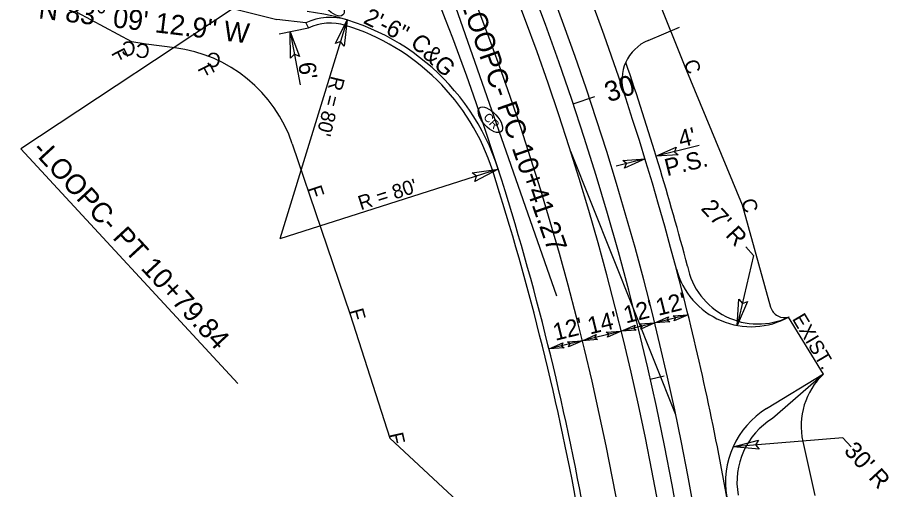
# Model space of a CAD drawing. Extents: x 1702862 to 1704514, y 793768 to 796215.
# Drawn here: x 1703743.4 to 1704047.6, y 794306.9 to 794472 of the extents above; entities that cross this region are included whole.
import ezdxf

# ---------------------------------------------------------------- set-up
doc = ezdxf.new("R2010")
doc.units = 0
for name, color, linetype in [('Prop Conc 2ft 6in Curb and Gutter', 7, 'Continuous'), ('Prop Dimension', 7, 'Continuous'), ('Prop Dimension Text', 7, 'Continuous'), ('Prop DSN Text', 7, 'Continuous'), ('Prop EOT', 7, 'Continuous'), ('Prop Horizontal Alignment', 7, 'Continuous'), ('Prop Horizontal Alignment Curve and Spiral Data', 7, 'Continuous'), ('Prop Horizontal Alignment Direction Label', 7, 'Continuous'), ('Prop Horizontal Alignment Station Label', 7, 'Continuous'), ('Prop Horizontal Alignment Tick Label', 7, 'Continuous'), ('Prop Horizontal Alignment Tick Large', 7, 'Continuous'), ('Prop Horizontal Alignment Tick Small', 7, 'Continuous'), ('Prop Lane Lines', 7, 'Continuous'), ('Prop Paved Shoulder', 7, 'Continuous'), ('Prop SS Cut Line', 7, 'Continuous'), ('Prop SS Fill Line', 7, 'Continuous'), ('Prop SS Misc', 7, 'Continuous'), ('Prop SS Transition Line', 7, 'Continuous'), ('Prop Terminator CELL', 7, 'Continuous'), ('Prop WCR CELL', 7, 'Continuous')]:
    doc.layers.add(name, color=color, linetype=linetype)

msp = doc.modelspace()

# ---------------------------------------------------------------- linework, layer by layer
at = {"layer": 'Prop Conc 2ft 6in Curb and Gutter'}
for centre, radius, start, end in [((1703852.67, 794451.95), 18, 72.9584, 115.227), ((1703835.09, 794394.58), 78, 17.697, 72.9584), ((1702989.11, 794124.65), 966, 10.14602, 17.69698)]:
    msp.add_arc(centre, radius, start, end, dxfattribs=at)
at = {"layer": 'Prop Dimension'}
for p, q in [((1703858.53, 794471.07), (1703835.09, 794394.58)), ((1703845, 794468.23), (1703834.87, 794466.1)), ((1703838.68, 794466.9), (1703842.13, 794448.38)), ((1703981.48, 794427.14), (1703966.46, 794423.44)), ((1703962.57, 794422.48), (1703952.5, 794420)), ((1703911.3, 794418.9), (1703835.09, 794394.58)), ((1703977.58, 794368.05), (1703960.1, 794363.75)), ((1703960.1, 794363.75), (1703929.03, 794356.1))]:
    msp.add_line(p, q, dxfattribs=at)
for points in [[(1703997.7, 794391.74), (1704000.49, 794388.71), (1703994.76, 794364.3)], [(1704034.48, 794321.92), (1704031.62, 794325.02), (1703993.3, 794321.91)]]:
    msp.add_lwpolyline(points, dxfattribs=at)
at = {"layer": 'Prop EOT'}
for p, q in [((1703844.15, 794470.04), (1703845, 794468.23)), ((1703963.67, 794463.92), (1703974.65, 794468.55)), ((1704024.85, 794347.32), (1704012.71, 794367.19)), ((1704024.85, 794347.32), (1704005.02, 794335.21))]:
    msp.add_line(p, q, dxfattribs=at)
for centre, radius, start, end in [((1702989.11, 794124.65), 1018, 14.75888, 42.70907), ((1703835.09, 794394.58), 80, 17.697, 83.1536), ((1703852.67, 794451.95), 20, 72.9584, 115.227), ((1703969.5, 794450.1), 15, 112.8746, 198.3644), ((1702989.11, 794124.65), 968, 10.14602, 17.69698), ((1703999.63, 794390.86), 27, 194.7589, 299.2661), ((1704020.66, 794309.61), 30, 121.4124, 190.1653)]:
    msp.add_arc(centre, radius, start, end, dxfattribs=at)
at = {"layer": 'Prop Horizontal Alignment'}
msp.add_arc((1702989.11, 794124.65), 1000, 351.25916, 42.70907, dxfattribs=at)
at = {"layer": 'Prop Horizontal Alignment Curve and Spiral Data'}
msp.add_line((1703744.62, 794426.04), (1703820.33, 794344.01), dxfattribs=at)
at = {"layer": 'Prop Horizontal Alignment Station Label'}
msp.add_line((1703836.77, 794487.04), (1703744.62, 794426.04), dxfattribs=at)
msp.add_lwpolyline([(1703895.55, 794478.02), (1703931.64, 794374.68)], dxfattribs=at)
at = {"layer": 'Prop Horizontal Alignment Tick Large'}
msp.add_line((1703937.48, 794441.8), (1703945.07, 794444.34), dxfattribs=at)
at = {"layer": 'Prop Horizontal Alignment Tick Small'}
msp.add_line((1703964.41, 794345.53), (1703969.29, 794346.64), dxfattribs=at)
at = {"layer": 'Prop Lane Lines'}
msp.add_line((1703973.28, 794333.07), (1703936.62, 794425.07), dxfattribs=at)
for radius, start, end in [(1006, 0.00687, 42.70907), (994, 359.40932, 42.70907), (980, 359.40932, 42.70907), (968, 17.6382, 31.00789), (1018, 10.1653, 14.75888)]:
    msp.add_arc((1702989.11, 794124.65), radius, start, end, dxfattribs=at)
at = {"layer": 'Prop Paved Shoulder'}
for p, q in [((1703803.86, 794478.91), (1703834.03, 794471.26)), ((1703844.15, 794470.04), (1703834.03, 794471.26)), ((1704024.85, 794347.32), (1704007.11, 794331.8))]:
    msp.add_line(p, q, dxfattribs=at)
for centre, radius, start, end in [((1702989.11, 794124.65), 1022, 14.75888, 18.93305), ((1704001.96, 794389.87), 25.05, 191.2148, 295.722), ((1704020.66, 794309.61), 26, 121.4124, 190.1653)]:
    msp.add_arc(centre, radius, start, end, dxfattribs=at)
at = {"layer": 'Prop SS Cut Line'}
for p, q in [((1703788.36, 794462.65), (1703783.41, 794463.43)), ((1703976.48, 794454.84), (1703996.51, 794406.41)), ((1703996.51, 794406.41), (1704006.42, 794370.71)), ((1704017.63, 794323.78), (1704021.82, 794304.82))]:
    msp.add_line(p, q, dxfattribs=at)
for centre, radius, start, end in [((1704011.24, 794372.05), 5, 195.5278, 288.5337), ((1704042.04, 794329.17), 25, 133.4523, 192.4595)]:
    msp.add_arc(centre, radius, start, end, dxfattribs=at)
at = {"layer": 'Prop SS Fill Line'}
for p, q in [((1703788.36, 794462.65), (1703783.41, 794463.43)), ((1703839.4, 794427.8), (1703859.6, 794368.12)), ((1703859.6, 794368.12), (1703873.4, 794324.92)), ((1703873.4, 794324.92), (1703911.44, 794289.63))]:
    msp.add_line(p, q, dxfattribs=at)
msp.add_arc((1703792.04, 794411.78), 50, 18.6944, 82.73, dxfattribs=at)
at = {"layer": 'Prop SS Transition Line'}
for p, q in [((1703957.17, 794503.16), (1703976.48, 794454.84)), ((1703783.41, 794463.43), (1703764.24, 794473.69)), ((1703798.37, 794461.37), (1703788.36, 794462.65))]:
    msp.add_line(p, q, dxfattribs=at)
at = {"layer": 'Prop Terminator CELL'}
for points in [[(1703854.47, 794462.89), (1703858.53, 794471.07), (1703857.47, 794461.94), (1703856.27, 794463.5)], [(1703838.81, 794457.77), (1703838.68, 794466.9), (1703841.91, 794458.3), (1703840.13, 794459.14)], [(1703974.08, 794423.96), (1703966.34, 794423.41), (1703973.48, 794426.57), (1703972.86, 794425.01)], [(1703954.82, 794421.93), (1703962.57, 794422.48), (1703955.42, 794419.32), (1703956.05, 794420.87)], [(1703902.25, 794417.67), (1703911.3, 794418.9), (1703903.16, 794414.65), (1703903.77, 794416.52)], [(1703998.33, 794372.71), (1703994.76, 794364.3), (1703995.27, 794373.48), (1703996.57, 794372)], [(1703971.17, 794365.56), (1703965.93, 794365.18), (1703970.76, 794367.32), (1703970.34, 794366.27)], [(1703972.34, 794367.68), (1703977.58, 794368.05), (1703972.75, 794365.92), (1703973.17, 794366.97)], [(1703959.52, 794362.69), (1703954.28, 794362.32), (1703959.11, 794364.45), (1703958.69, 794363.4)], [(1703960.69, 794364.81), (1703965.93, 794365.18), (1703961.1, 794363.05), (1703961.52, 794364.1)], [(1703945.92, 794359.34), (1703940.68, 794358.97), (1703945.52, 794361.11), (1703945.09, 794360.05)], [(1703949.04, 794361.94), (1703954.28, 794362.32), (1703949.44, 794360.18), (1703949.87, 794361.23)], [(1703934.27, 794356.47), (1703929.03, 794356.1), (1703933.86, 794358.24), (1703933.44, 794357.18)], [(1703935.45, 794358.6), (1703940.68, 794358.97), (1703935.85, 794356.83), (1703936.27, 794357.88)], [(1704002.39, 794321.09), (1703993.3, 794321.91), (1704002.19, 794324.24), (1704001.17, 794322.55)]]:
    msp.add_lwpolyline(points, close=True, dxfattribs=at)
at = {"layer": 'Prop WCR CELL'}
for centre in [(1703853.29, 794476.93), (1703908.58, 794436.18)]:
    msp.add_ellipse(centre, major_axis=(3.8, -4.12), ratio=0.462467, dxfattribs=at)

# ---------------------------------------------------------------- texts
at = {"layer": 'Prop Dimension'}
for s, rotation, p in [("6'", 277.2204, (1703841.5, 794456.01)), ("27' R", 312.7091, (1703981.78, 794405.02)), ("30' R", 312.7091, (1704031.72, 794320.26))]:
    msp.add_text(s, height=6, rotation=rotation, dxfattribs=at).set_placement(p)
at = {"layer": 'Prop Dimension Text'}
for s, height, rotation, p in [('2\'-6"  ', 6, 333.7051, (1703863.86, 794470.13)), (' C&G', 6, 316.9422, (1703878.61, 794464.12)), ("R = 80'", 5, 256.066, (1703852.94, 794451.76)), ("4'", 6, 13.8336, (1703975.02, 794426.41)), ('P.S.', 6, 13.8336, (1703970.23, 794416.44)), ("R = 80'", 5, 17.6451, (1703863.31, 794404.55)), ("12'", 6, 13.8336, (1703967.17, 794367.64)), ("12'", 6, 13.8336, (1703955.88, 794364.97)), ("14'", 6, 13.8336, (1703943.32, 794361.11)), ("12'", 6, 13.8336, (1703931.24, 794358.9))]:
    msp.add_text(s, height=height, rotation=rotation, dxfattribs=at).set_placement(p)
at = {"layer": 'Prop DSN Text'}
msp.add_text('EXIST.', height=5, rotation=300.6784, dxfattribs=at).set_placement((1704013.78, 794366.61))
at = {"layer": 'Prop Horizontal Alignment Direction Label'}
msp.add_text('N 83%%d 09\' 12.9" W', height=7, rotation=353.1536, dxfattribs=at).set_placement((1703750.58, 794471.66))
at = {"layer": 'Prop Horizontal Alignment Station Label'}
for s, rotation, p in [('-LOOPC- PC 10+41.27', 289.3057, (1703897.04, 794480.4)), ('-LOOPC- PT 10+79.84', 312.7091, (1703748.16, 794425.42))]:
    msp.add_text(s, height=7, rotation=rotation, dxfattribs=at).set_placement(p)
at = {"layer": 'Prop Horizontal Alignment Tick Label'}
msp.add_text('30', height=7, rotation=18.4908, dxfattribs=at).set_placement((1703949.82, 794442.22))
at = {"layer": 'Prop SS Misc'}
for s, rotation, p in [('C', 173.1536, (1703784.94, 794463.25)), ('F', 296.9289, (1703776.03, 794459.54)), ('C', 173.1536, (1703789.88, 794462.47)), ('C', 173.1536, (1703814.68, 794459.3)), ('C', 288.4908, (1703975.99, 794456.3)), ('F', 296.9289, (1703806.15, 794454.06)), ('F', 288.4908, (1703844.67, 794412.25)), ('C', 285.626, (1703996.09, 794407.89)), ('F', 285.626, (1703859.22, 794369.48)), ('F', 282.7612, (1703873.09, 794326.31))]:
    msp.add_text(s, height=5, rotation=rotation, dxfattribs=at).set_placement(p)
at = {"layer": 'Prop WCR CELL'}
msp.add_text('CR', height=3, rotation=312.7091, dxfattribs=at).set_placement((1703905.9, 794436.91))

doc.saveas('drawing.dxf')
